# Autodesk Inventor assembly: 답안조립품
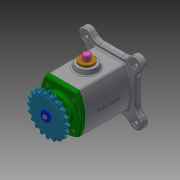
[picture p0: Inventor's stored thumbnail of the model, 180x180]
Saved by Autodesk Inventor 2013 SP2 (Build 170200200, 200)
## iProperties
Created: 2022-01
Part Number: 답안조립품
Document SubType Name: Assembly
Designer: i
Author: i
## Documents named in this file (13)
- C:\Users\i\Desktop\720106V1019\답안조립품.iam
- C:\Users\i\Desktop\720106V1019\본체.ipt
- C:\Users\i\Desktop\720106V1019\베어링 6203.ipt
- C:\Users\i\Desktop\720106V1019\볼트 M4 x 12.ipt
- C:\Users\i\Desktop\720106V1019\부시.ipt
- C:\Users\i\Desktop\720106V1019\스프로킷.ipt
- C:\Users\i\Desktop\720106V1019\슬라이더.ipt
- C:\Users\i\Desktop\720106V1019\오일 실 17 x 30 x 8.ipt
- C:\Users\i\Desktop\720106V1019\와셔 4 x 20.ipt
- C:\Users\i\Desktop\720106V1019\육각머리볼트 M4.ipt
- C:\Users\i\Desktop\720106V1019\커버.ipt
- C:\Users\i\Desktop\720106V1019\키 5 x 5.ipt
- C:\Users\i\Desktop\720106V1019\편심축.ipt
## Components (8 placed, 1 different names)
1. M4x0.7x12:1
2. M4x0.7x12:2
3. M4x0.7x12:3
4. M4x0.7x12:4
5. M4x0.7x12:5
6. M4x0.7x12:6
7. M4x0.7x12:7
8. M4x0.7x12:8
